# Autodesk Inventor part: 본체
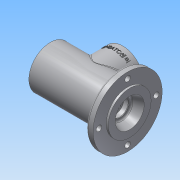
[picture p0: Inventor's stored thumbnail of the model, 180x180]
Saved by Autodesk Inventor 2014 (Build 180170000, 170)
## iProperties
Created: 2016-08
Part Number: 본체
Material: 알루미늄 6061
Document SubType Name: Modeling
Designer: 703
Density: 2.71 g/cm^3
Appearance: 알루미늄 - 평지
Mass: 730.757 g
Surface Area: 616.334 cm^2
Volume: 269.652 cm^3
Author: 703
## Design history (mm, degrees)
sketch "스케치1"
  geometry: L1 (-57.5, 0)-(-57.5, 31); L2 (-57.5, 31)-(57.5, 31); L3 (57.5, 31)-(57.5, 21); L4 (57.5, 0)-(-57.5, 0); L5 (-48.5, 0)-(-48.5, 24); L6 (-48.5, 24)-(-45.5, 24); L7 (-45.5, 24)-(-45.5, 20); L8 (-45.5, 20)-(-36.5, 20); L9 (-36.5, 20)-(-36.5, 17.5); L10 (-36.5, 17.5)-(-33.25, 17.5); L11 (-33.25, 17.5)-(-33.25, 18.5); L12 (-33.25, 18.5)-(-31.5, 18.5); L13 (-31.5, 18.5)-(-31.5, 17.5); L14 (28.5, 17.2)-(28.5, 16.5); L15 (28.5, 16.5)-(30.5, 16.5); L16 (33.5, 13.5)-(33.5, 10); L17 (33.5, 10)-(36.2, 10); L18 (36.2, 10)-(36.2, 12.2); L19 (36.5, 12.5)-(42.8, 12.5); L20 (43.5, 12.904)-(43.5, 16); L21 (43.5, 16)-(57.5, 21); L22 (42.8, 12.5)-(43.5, 12.904); L23 (57.5, 21)-(57.5, 0); L24 (-20.5, 18.5)-(-20.5, 23); L25 (-17.5, 26)-(14.5, 26); L26 (17.5, 23)-(17.5, 18.5); L27 (-31.5, 17.5)-(-21.5, 17.5); L28 (18.5, 17.5)-(28.2, 17.5); L29 (-1.5, 26)-(-1.5, 0); L30 (-21.5, 17.5)-(-20.5, 18.5); L31 (17.5, 18.5)-(18.5, 17.5); A1 r 0.3 centre (28.2, 17.2) between (28.5, 17.2) and (28.2, 17.5); A2 r 0.3 centre (36.5, 12.2) between (36.5, 12.5) and (36.2, 12.2); A3 r 3 centre (-17.5, 23) between (-17.5, 26) and (-20.5, 23); A4 r 3 centre (14.5, 23) between (17.5, 23) and (14.5, 26); A5 r 3 centre (30.5, 13.5) between (33.5, 13.5) and (30.5, 16.5); 7 further points
  constraints: 62 end point, 18 parallel, 12 point on line, 11 tangent, 10 point on circle, 8 perpendicular, 5 centre point, 2 equal radius, 2 midpoint, 1 coincident, 1 vertical
  dimensions: "d1" = 62 diameter of L2 L4; "d2" = 48 diameter of L6 L4; "d3" = 40 diameter of L8 L4; "d4" = 35 diameter of L10 L4; "d5" = 37 diameter of L12 L4; "d7" = 33 diameter of L15 L4; "d8" = 20 diameter of L17 L4; "d9" = 25 diameter of L19 L4; "d10" = 32 diameter of L20.end L4; "d11" = 42 diameter of L3.end L4; "d12" = 14 distance between parallel lines of L3 L20; "d13" = 7.3 distance of point (36.2, 12.5) point (43.5, 12.5); "d14" = 2.7 distance of L16.end L17.end; "d15" = 60 distance between parallel lines of L14 L13; "d16" = 3 distance between parallel lines of L5 L7; "d17" = 9 distance between parallel lines of L9 L7; "d18" = 1.75 distance of L11.end L12.end; "d19" = 5 distance between parallel lines of L9 L13; "d20" = 21 distance between parallel lines of L1 L9; "d21" = 0.3 radius of A1; "d22" = 0.7 distance of L19.end point (43.5, 12.5); "d23" = 30 deg angle of L19 L22; "d41" = 38 distance between parallel lines of L26 L24; "d42" = 52 diameter of L25 L4; "d43" = 35 diameter of L27 L4; "d44" = 3 radius of A3; "d61" = 115 distance between parallel lines of L3 L1; "d62" = 56 distance between parallel lines of L1 L29; "d63" = 19 distance between parallel lines of L29 L24; "d106" = 3 radius of A5; "d107" = 1 distance of L27.end point (-20.5, 17.5); "d108" = 45 deg angle of L27 L30; "d109" = 1 distance of L26.end point (17.5, 17.5) (= d107); "d110" = 45 deg angle of L26 L31 (= d108)
revolve "회전1" sketch "스케치1" stored, may be unused: angle "d24" = 90 deg
fillet "모깎기1" dims "d25" = 3
hole "구멍1" diameter "d28" = 40.376; stored, may be unused: countersink angle "d32" = 90 deg, drill point angle "d34" = 0 deg; dims "d26" = 10, "d27" = 10, "d29" = 6, "d30" = 4, "d31" = 2, "d33" = 9
node "작업 평면1"
node "작업 평면2"
sketch "스케치6"
  geometry: C1 r 30 at (1.5, 0); 1 further point
  constraints: 1 centre point, 1 horizontal alignment
  dimensions: "d65" = 60 diameter of C1; "d66" = 1.5 distance of point (0, 0) C1.centre
extrude "돌출3" join sketch "스케치6" stored distance "d67" = 10; taper "d68" = 0 deg
sketch "스케치7"
  geometry: C1 r 30 at (0, 0) reference; C2 r 19 at (0, 0); 1 further point
  constraints: 1 centre point, 1 coincident
  dimensions: "d69" = 38 diameter of C2
extrude "돌출4" cut sketch "스케치7" distance "d70" = 50; taper "d71" = 0 deg
sketch "스케치8"
  geometry: C1 r 19 at (0, 0) reference; 2 further points
  constraints: 1 vertical alignment
  dimensions: "d72" = 24 distance of C1.centre point (0, 24)
hole "구멍3" sketch "스케치8" at (0, 24) diameter "d73" = 3.242; stored, may be unused: countersink angle "d77" = 90 deg, drill point angle "d79" = 118 deg; dims "d74" = 8, "d75" = 4, "d76" = 2, "d78" = 10
node "작업 평면3"
sketch "스케치9"
  geometry: L1 (-56, -80)-(-56, -18) reference; L2 (-30, 0)-(30, 0) reference; 2 further points
  constraints: 1 other
  dimensions: "d83" = 56 distance from line of L1 point (0, -10); "d85" = 10 distance from line of L2 point (0, -10)
feature "엠보싱1" sketch "스케치9" dims "d86" = 0.5, "d87" = 0
node "작업 평면4"
sketch "스케치10"
  geometry: C1 r 19.929 at (0, 0) reference; C2 r 31 at (0, 0) reference; C3 r 50 at (0, 0); C4 r 4 at (0, 41.5); C5 r 4 at (-41.5, 0); C6 r 4 at (41.5, 0); C7 r 4 at (0, -41.5); 1 further point
  constraints: 5 centre point, 2 horizontal alignment, 2 vertical alignment, 1 coincident
  dimensions: "d89" = 100 diameter of C3; "d90" = 8 diameter of C4; "d91" = 41.5 distance of point (0, 0) C4.centre; "d92" = 8 diameter of C5; "d93" = 8 diameter of C6; "d94" = 8 diameter of C7; "d95" = 41.5 distance of point (0, 0) C5.centre; "d96" = 41.5 distance of point (0, 0) C6.centre (= d95); "d97" = 41.5 distance of point (0, 0) C7.centre (= d96)
extrude "돌출5" join sketch "스케치10" distance "d98" = 10; taper "d99" = 0 deg
fillet "모깎기2" dims "d100" = 3
fillet "모깎기3" dims "d101" = 3
fillet "모깎기4" dims "d102" = 3
chamfer "모따기2" distance "d103" = 1; stored, may be unused: second distance "d104" = 2, angle "d105" = 45 deg
node "솔리드1"
pattern_circular "원형 패턴2" dims angle "d81" = 360 deg
node "절단 모서리 투영2"
other parameters: "d6" = 35, "d35" = 49, "d64" = 49, "d88" = -3
